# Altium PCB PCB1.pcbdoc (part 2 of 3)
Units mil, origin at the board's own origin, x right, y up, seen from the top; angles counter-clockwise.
Board outline 3256.12 x 1802.31 mil, 4 copper layers (Top Layer, Inner1, Inner2, Bottom Layer); 101 components, 70 nets, 295 pads, 151 vias.
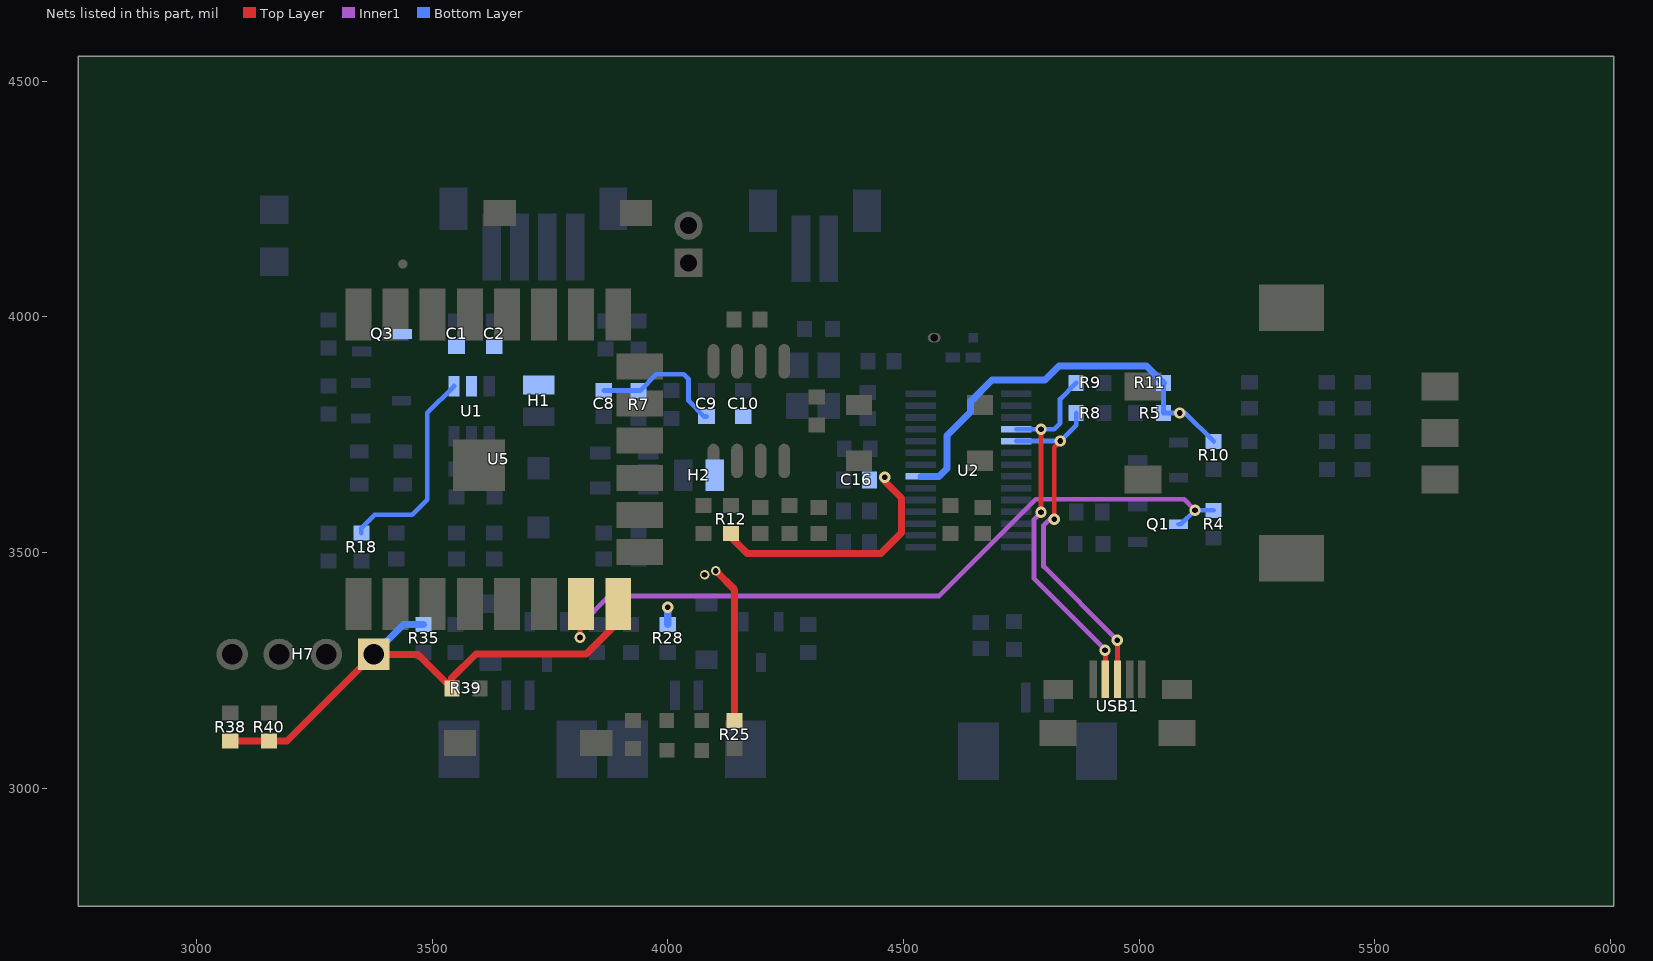
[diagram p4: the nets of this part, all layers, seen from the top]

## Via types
v1: diameter 20, hole 12.01, Top Layer to Bottom Layer, 104 vias
v2: diameter 24.02, hole 12.01, Top Layer to Bottom Layer, 44 vias
v3: diameter 20, hole 12, Top Layer to Bottom Layer, 3 vias

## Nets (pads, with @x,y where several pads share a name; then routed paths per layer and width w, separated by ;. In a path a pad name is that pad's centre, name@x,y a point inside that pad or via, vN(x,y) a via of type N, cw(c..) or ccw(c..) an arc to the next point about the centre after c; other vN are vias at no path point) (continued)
TXD: Q1.3 R4.2 U5.7 | length 1609.7
  Top Layer w10: v2(3814.01,3320) 3814.01,3388.7 U5.7@3816.23,3390.91
  Inner1 w10: v2(3814.01,3320) 3814.01,3346 3876.01,3408 4575.72,3408 4781.01,3613.29 5095.06,3613.29 v2(5118.35,3590)
  Bottom Layer w10: Q1.3@5083.37,3560 5088.35,3560 v2(5118.35,3590) 5118.69,3589.66 R4.2@5158.01,3589.66
USB_DM: R9.1 U2.18 USB1.2 | length 795.9
  Top Layer w10: v2(4791.83,3585.18) v2(4791.83,3761.5) ; v2(4927.59,3292.49) 4928.41,3291.67 USB1.2@4928.41,3231.18
  Inner1 w10: v2(4791.83,3585.18) 4777,3570.35 4777,3444.63 v2@4927.59,3294.03
  Bottom Layer w10: U2.18@4739.19,3761.5 v2(4791.83,3761.5) 4819.51,3761.5 4832.01,3774 4832.01,3825.66 R9.1@4866.35,3860
USB_DP: R8.1 U2.19 USB1.3 | length 757.6
  Top Layer w10: v2(4819.68,3570.6) 4819.68,3723.68 v2(4832.51,3736.5) ; v2(4953.57,3314.11) 4954.01,3313.68 USB1.3@4954.01,3231.18
  Inner1 w10: v2(4819.68,3570.6) 4809.77,3570.6 4797.08,3557.91 4797.08,3470.61 v2(4953.57,3314.11)
  Bottom Layer w10: U2.19@4739.19,3736.5 v2(4832.51,3736.5) 4866.35,3770.34 R8.1@4866.35,3796
VCC: C8.2 C9.2 C10.2 H2.2 H7.1 R7.2 R25.2 R28.2 R35.2 R38.2 R39.2 R40.2 U5.8 | length 1836.8
  Top Layer w15: R38.2@3072.01,3100.34 R40.2@3154.01,3100.34 3192.35,3100.34 H7.1@3376.01,3284 3470.35,3284 R39.2@3541.35,3213 ; R39.2@3542.35,3212 R39.2@3541.35,3213 ; U5.8@3894.97,3390.91 3893.97,3389.91 3893.97,3351.96 3827.01,3285 3593.01,3285 3541.35,3233.34 R39.2@3541.35,3213 ; v3(4102.01,3461) 4142.01,3421 R25.2@4142.01,3143.66
  Bottom Layer w10: C8.2@3864.01,3843.56 3937.92,3843.56 R7.2@3938.01,3843.47 3941.48,3843.47 3976.01,3878 4034.01,3878 4044.01,3868 4044.01,3822 4077.56,3788.44 C9.2@4082.06,3788.44
  Bottom Layer w15: H7.1@3376.01,3284 3439.67,3347.66 R35.2@3482.01,3347.66 ; R28.2@4000.01,3347.66 v2(4000.01,3384)
  other v3: 4078.01,3453
VDDIO: C16.2 R5.1 R10.1 R11.1 R12.1 U2.7 | length 1411.5
  Top Layer w15: R12.1@4134.01,3540.53 4134.01,3532.53 4168.14,3498.4 4452.63,3498.4 4496.14,3541.91 4496.14,3615.87 4460.01,3652 v2(4460.01,3660)
  Bottom Layer w10: R11.1@5051.67,3860 R5.1@5051.67,3796 v2(5086.01,3796) 5097.67,3796 R10.1@5158.01,3735.66
  Bottom Layer w15: U2.7@4536.83,3661.5 4575.51,3661.5 4592.01,3678 4592.01,3748 4642.01,3798 4642.01,3820 4688.01,3866 4800.01,3866 4830.01,3896 5015.67,3896 R11.1@5051.67,3860
VIN: C1.2 C2.2 H1.1 Q3.3 R18.2 U1.4 U1.5 | length 440
  Bottom Layer w10: R18.2@3350.01,3541.47 3350.01,3552 3378.01,3580 3458.01,3580 3490.01,3612 3490.01,3796.55 U1.4@3546.61,3853.15
pads on no net: H5.3 H5.4 H6.5 H6.6 H8.3 H8.4 H9.3 H9.4 SW1.2 SW2. U1.6 U2.5 U2.10 U4.7 U5.1 U5.11 U5.12 U5.14 U5.17 U5.18 U5.19 U5.20 U5.21 U5.22 U5.23 USB1.4 USB1.6 USB1.7 USB1.8 USB1.9

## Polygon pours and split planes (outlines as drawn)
GND on Bottom Layer (solid, remove dead copper, pour order 2): 3000,4023.76 3228.61,4023.76 3228.61,3371.05 3000,3371.05 3000,3002.82 5753.19,3002.82 5756.01,3000 5756.01,4302.03 5547,4302.03 5547,3966 4456.01,3966 4456.01,4302.24 3000,4302.24
GND on Top Layer (solid, remove dead copper, pour order 0): 3000,4023.76 3228.61,4023.76 3228.61,3371.05 3000,3371.05 3000,3002.82 5753.19,3002.82 5756.01,3000 5756.01,4302.03 5547,4302.03 5547,3966 4456.01,3966 4456.01,4302.24 3000,4302.24

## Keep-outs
Board Outline Layer:
  region: 5267.93,3120.93 cw(c5224.62,3120.93) 5181.32,3120.93 cw(c5224.62,3120.93)
  region: 5681.32,4183.94 cw(c5638.01,4183.94) 5594.7,4183.94 cw(c5638.01,4183.94)
  region: 3378.17,4183.94 cw(c3334.86,4183.94) 3291.55,4183.94 cw(c3334.86,4183.94)
  region: 3502.18,3120.93 cw(c3472.66,3120.93) 3443.13,3120.93 cw(c3472.66,3120.93)
  region: 3378.17,3120.93 cw(c3334.86,3120.93) 3291.55,3120.93 cw(c3334.86,3120.93)
  region: 3443.13,4183.94 cw(c3472.66,4183.94) 3502.18,4183.94 cw(c3472.66,4183.94)
  region: 5471.13,4183.94 cw(c5500.66,4183.94) 5530.18,4183.94 cw(c5500.66,4183.94)
  lines w1: 3291.55,3120.93 ccw(c3334.86,3120.93) 3378.17,3120.93 ccw(c3334.86,3120.93) 3291.55,3120.93 ; 3291.55,4183.94 ccw(c3334.86,4183.94) 3378.17,4183.94 ccw(c3334.86,4183.94) 3291.55,4183.94 ; 3443.13,3120.93 ccw(c3472.66,3120.93) 3502.18,3120.93 ccw(c3472.66,3120.93) 3443.13,3120.93 ; 3443.13,4183.94 cw(c3472.66,4183.94) 3502.18,4183.94 cw(c3472.66,4183.94) 3443.13,4183.94 ; 5181.32,3120.93 ccw(c5224.62,3120.93) 5267.93,3120.93 ccw(c5224.62,3120.93) 5181.32,3120.93 ; 5471.13,4183.94 cw(c5500.66,4183.94) 5530.18,4183.94 cw(c5500.66,4183.94) 5471.13,4183.94 ; 5594.7,4183.94 ccw(c5638.01,4183.94) 5681.32,4183.94 ccw(c5638.01,4183.94) 5594.7,4183.94
  lines w3.9: 3000,3002.82 3000,3371.05 3228.61,3371.05 3228.61,4023.76 3000,4023.76 3000,4302.03
  lines w3.94: 3000.01,4302 4548.55,4302.25 ccw(c5048.06,5262.81) 5547.22,4302.07 5756.12,4302.03 5756.12,3317.78 5271.12,3002.82 4537.6,3002.82 4537.6,3046.31 ccw(c4380.12,3046.64) 4222.64,3046.34 4222.72,3002.82 3000.21,3002.82

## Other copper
Top Layer:
  region net VCC: 3866.01,3446 4012.01,3446 4038.01,3472 4110.01,3472 4116.01,3466 4116.01,3438 4110.01,3432 4050.01,3432 4034.01,3416 4034.01,3350 4020.01,3336 3866.01,3336
  region net $1N6443: 4189.51,3633.81 4204.51,3633.81 ccw(c4236.58,3633.81) 4213.72,3611.31 4178.29,3611.31 ccw(c4161.33,3633.81)
  region net DACL: 4352.72,3594.54 4352.72,3584.54 ccw(c4352.72,3558.36) 4337.72,3579.81 4337.72,3602.04 ccw(c4352.72,3613.29)
  region net $1N6492: 4279.79,3533.03 4279.79,3548.03 ccw(c4279.79,3583.15) 4302.29,3556.19 4302.29,3524.69 ccw(c4279.79,3498.52)
  region net VCC: 3431.97,3291.5 3431.97,3276.5 ccw(c3431.97,3248.38) 3409.47,3265.25 3409.47,3302.75 ccw(c3431.97,3319.62)
  region net VCC: 3345.19,3242.58 3334.59,3253.19 ccw(c3302.77,3277.05) 3342.54,3277.05 3369.06,3250.54 ccw(c3369.06,3210.76)
  region net LOG_RXD: 3183.51,3238.44 3168.51,3238.44 3168.4,3240.79 3168.11,3242.86 3167.64,3244.69 3166.99,3246.31 3166.2,3247.76 3165.26,3249.07 3163.01,3251.4 3160.34,3253.58 3157.37,3255.87 3154.19,3258.54 3150.91,3261.87 3201.1,3261.87 3197.82,3258.54 3194.64,3255.87 3191.67,3253.58 3189.01,3251.4 3186.75,3249.07 3185.82,3247.76 3185.02,3246.31 3184.38,3244.69 3183.9,3242.86 3183.61,3240.79
  region net LOG_RXD: 3196.01,3317.5 3222.16,3302.5 3220.58,3302.4 3219.1,3302.11 3217.72,3301.64 3216.46,3301 3215.29,3300.21 3214.23,3299.28 3213.28,3298.23 3212.43,3297.05 3211.05,3294.42 3210.09,3291.47 3209.56,3288.32 3209.45,3285.07 3170.44,3317 3174.27,3317.56 3177.55,3317.87 3180.45,3317.98 3183.16,3317.95 3188.81,3317.69
  region net LOG_TXD: 3083.51,3238.44 3068.51,3238.44 3068.4,3240.79 3068.11,3242.86 3067.64,3244.69 3066.99,3246.31 3066.2,3247.76 3065.26,3249.07 3063.01,3251.4 3060.34,3253.58 3057.37,3255.87 3054.19,3258.54 3050.91,3261.87 3101.1,3261.87 3097.82,3258.54 3094.64,3255.87 3091.67,3253.58 3089.01,3251.4 3086.75,3249.07 3085.82,3247.76 3085.02,3246.31 3084.38,3244.69 3083.9,3242.86 3083.61,3240.79
  region net LOG_TXD: 3102.92,3321.52 3113.52,3310.91 3111.94,3309.18 3110.68,3307.51 3109.72,3305.88 3109.03,3304.28 3108.57,3302.69 3108.31,3301.1 3108.25,3297.86 3108.59,3294.44 3109.08,3290.72 3109.43,3286.58 3109.4,3281.9 3073.91,3317.4 3078.58,3317.43 3082.72,3317.07 3086.44,3316.59 3089.87,3316.24 3093.11,3316.3 3094.7,3316.56 3096.28,3317.02 3097.89,3317.72 3099.52,3318.68 3101.19,3319.93
  region net $1N6556: 4204.51,3954.49 4189.51,3954.49 ccw(c4158.55,3954.49) 4179.81,3976.99 4211.31,3976.99 ccw(c4245.12,3954.49)
  region net +5V: 4108.72,3984.5 4108.72,3999.5 ccw(c4108.72,4016.48) 4124.7,4010.75 4124.7,3976.99 ccw(c4108.72,3963.74)
  region net $1N8074: 4102.76,3085.53 4102.76,3075.53 ccw(c4102.76,3056.78) 4087.76,3068.03 4087.76,3093.03 ccw(c4102.76,3104.28)
  region net $1N8184: 3967.4,3079.34 3967.4,3089.34 ccw(c3967.4,3109.03) 3982.4,3096.28 3982.4,3071.84 ccw(c3967.4,3060.59)
  region net $1N6373: 4115.51,3607.35 4115.51,3592.35 ccw(c4115.51,3557.94) 4093.01,3583.98 4093.01,3615.73 ccw(c4115.51,3641.76)
  region net $1N6373: 4089.23,3623.68 4100.97,3614.21 ccw(c4132.79,3590.35) 4093.01,3590.35 4065.36,3615.73 ccw(c4065.36,3655.5)
  region net DACR: 4044,3536.01 4044,3546.01 ccw(c4044,3564.76) 4059,3553.51 4059,3528.51 ccw(c4044,3517.26)
  region net $1N6373: 4094.5,3592.35 4094.5,3607.35 ccw(c4094.5,3641.76) 4117,3615.73 4117,3583.98 ccw(c4094.5,3557.94)
  region net VDDIO: 4158.97,3518.18 4140.05,3515.89 ccw(c4117,3489.99) 4117,3524.66 4151.01,3542.04 ccw(c4190.79,3542.04)
  region net $1N6486: 4239.51,3638.23 4254.51,3638.23 ccw(c4282.63,3638.23) 4265.76,3615.73 4241,3615.73 ccw(c4070.6,3615.73)
  region net $1N6492: 4297.51,3548.03 4297.51,3533.03 ccw(c4297.51,3498.62) 4275.01,3524.66 4275.01,3556.41 ccw(c4297.51,3582.44)
  region net SPK-: 4287.16,3844.37 4302.43,3857.38 ccw(c4333.01,3890.95) 4333.01,3845.54 4299,3813.78 ccw(c4253.58,3813.78)
  region net $1N6486: 4276.5,3762.84 4276.5,3777.84 ccw(c4276.5,3812.25) 4299,3786.22 4299,3754.46 ccw(c4276.5,3728.43)
  region net VCC: 4134.51,3182.04 4149.51,3182.04 ccw(c4180.88,3182.04) 4159.01,3159.54 4125,3159.54 ccw(c4103.13,3182.04)
  region net $1N8074: 4110,3075.53 4110,3085.53 ccw(c4110,3104.28) 4125,3093.03 4125,3068.46 ccw(c4110,3056.06)
  region net SPK_LED: 3918.51,3175.45 3933.51,3175.45 ccw(c3951.59,3175.45) 3943.01,3159.54 3909,3159.54 ccw(c3900.42,3175.45)
  region net $1N8184: 3958.01,3089.34 3958.01,3079.34 ccw(c3958.01,3060.59) 3943.01,3071.84 3943.01,3096.84 ccw(c3958.01,3108.09)
  region net VCC: 3111.51,3107.84 3111.51,3092.84 ccw(c3111.51,3058.43) 3089.01,3084.46 3089.01,3116.22 ccw(c3111.51,3142.25)
  region net LOG_TXD: 3068.51,3198.04 3083.51,3198.04 ccw(c3132.22,3198.04) 3089.01,3175.54 3057.26,3175.54 ccw(c3040.38,3198.04)
  region net VCC: 3192.35,3107.84 3192.35,3092.84 ccw(c3192.35,3061.49) 3171.01,3084.46 3171.01,3116.22 ccw(c3192.35,3139.19)
  region net VCC: 3114.5,3092.84 3114.5,3107.84 ccw(c3114.5,3142.25) 3137,3116.22 3137,3084.46 ccw(c3114.5,3058.43)
  region net LOG_RXD: 3167.23,3183.49 3178.97,3174.02 ccw(c3210.79,3150.15) 3171.01,3150.15 3143.36,3175.54 ccw(c3143.36,3215.31)
  region net EC11_D: 5062.42,3660.27 5062.42,3650.27 ccw(c5062.42,3631.52) 5047.42,3642.77 5047.42,3667.77 ccw(c5062.42,3679.02)
  region net EC11_A: 5589.38,3696.79 5607.62,3692.69 ccw(c5629.7,3714.77) 5620.94,3684.8 5598.6,3684.8 ccw(c5548.09,3655.51)
  region net EC11_B: 5583.6,3847.13 5583.6,3857.13 ccw(c5583.6,3875.88) 5598.6,3864.63 5598.6,3839.63 ccw(c5583.6,3828.38)
  region net BOOT: 3449.82,4119.5 3449.82,4104.5 3447.65,4104.4 3445.62,4104.13 3442.07,4103.33 3439.44,4102.52 3438.01,4102.16 3438.01,4121.84 3439.44,4121.48 3442.07,4120.67 3445.62,4119.87 3447.65,4119.6
  region net RXD: 3821.23,3936.22 3811.23,3936.22 ccw(c3794.88,3936.22) 3803.73,3949.97 3828.73,3949.97 ccw(c3837.57,3936.22)
  region net VCC: 3880.45,3327.84 3859.45,3328.05 ccw(c3827.63,3351.92) 3867.41,3351.92 3904.32,3335.8 ccw(c3904.32,3296.02)
  region net TXD: 3819.01,3320.8 3809.01,3320.8 ccw(c3790.26,3320.8) 3801.51,3335.8 3826.51,3335.8 ccw(c3837.76,3320.8)
  region net SPK_LED: 3744.99,3318 3729.99,3318 ccw(c3710.28,3318) 3718.74,3335.8 3756.24,3335.8 ccw(c3764.69,3318)
  region net POWER_IO: 3651.24,3468.53 3666.24,3468.53 ccw(c3694.36,3468.53) 3677.49,3446.03 3639.99,3446.03 ccw(c3623.11,3468.53)
  region net POWER_SW: 3572.51,3468 3587.51,3468 ccw(c3614.58,3468) 3598.76,3446.03 3561.26,3446.03 ccw(c3545.43,3468)
  region net EN: 3493.77,3454.74 3508.77,3454.74 ccw(c3520.02,3457.65) 3520.02,3446.03 3482.52,3446.03 ccw(c3482.52,3457.65)
  region net POWER_ADC: 3418.51,3458 3433.51,3458 ccw(c3445.5,3458) 3444.76,3446.03 3407.26,3446.03 ccw(c3406.52,3458)
  region net LOG_TXD: 3296.24,3946.94 3304.38,3976.29 ccw(c3271.26,4009.41) 3316.22,3996.28 3316.22,3958.78 ccw(c3329.35,3913.82)
  region net LOG_RXD: 3406.62,3942.01 3387,3943.6 ccw(c3355.18,3967.47) 3394.96,3967.47 3430.49,3949.97 ccw(c3430.49,3910.19)
  region net POWER_LED: 3587.51,3936 3572.51,3936 ccw(c3558.21,3936) 3561.26,3949.97 3598.76,3949.97 ccw(c3601.8,3936)
  region net $1N6373: 4104.51,3647.58 4089.51,3647.58 4089.3,3651.73 4088.74,3655.7 4087.95,3659.38 4087.06,3662.67 4085.37,3667.72 4084.6,3670.08 4109.41,3670.08 4108.64,3667.72 4106.96,3662.67 4106.06,3659.38 4105.27,3655.7 4104.72,3651.73
  region net $1N6443: 4189.41,3704.39 4189.41,3684.39 4183.81,3684.39 4178.39,3684.26 4173.32,3683.82 4170.98,3683.41 4168.78,3682.86 4166.76,3682.13 4164.94,3681.2 4163.34,3680.04 4161.99,3678.64 4160.89,3676.97 4160.08,3675 4159.58,3672.71 4159.41,3670.08 4159.41,3718.7 4159.58,3716.07 4160.08,3713.78 4160.89,3711.81 4161.99,3710.14 4163.34,3708.74 4164.94,3707.58 4166.76,3706.65 4168.78,3705.92 4170.98,3705.37 4173.32,3704.96 4178.39,3704.52 4183.81,3704.39
  region net $1N6443: 4204.51,3647.58 4189.51,3647.58 4189.3,3651.73 4188.74,3655.7 4187.95,3659.38 4187.06,3662.67 4185.37,3667.72 4184.6,3670.08 4209.41,3670.08 4208.64,3667.72 4206.96,3662.67 4206.06,3659.38 4205.27,3655.7 4204.72,3651.73
  region net $1N6443: 4154.6,3684.39 4154.6,3704.39 4160.2,3704.39 4165.62,3704.52 4170.69,3704.96 4173.04,3705.37 4175.23,3705.92 4177.25,3706.65 4179.07,3707.58 4180.67,3708.74 4182.03,3710.14 4183.12,3711.81 4183.93,3713.78 4184.43,3716.07 4184.6,3718.7 4184.6,3670.08 4184.43,3672.71 4183.93,3675 4183.12,3676.97 4182.03,3678.64 4180.67,3680.04 4179.07,3681.2 4177.25,3682.13 4175.23,3682.86 4173.04,3683.41 4170.69,3683.82 4165.62,3684.26 4160.2,3684.39
  region net $1N6486: 4239.51,3741.2 4254.51,3741.2 4254.72,3737.05 4255.27,3733.08 4256.06,3729.4 4256.96,3726.11 4258.64,3721.06 4259.41,3718.7 4234.6,3718.7 4235.37,3721.06 4237.06,3726.11 4237.95,3729.4 4238.74,3733.08 4239.3,3737.05
  region net $1N6486: 4254.51,3647.58 4239.51,3647.58 4239.3,3651.73 4238.74,3655.7 4237.95,3659.38 4237.06,3662.67 4235.37,3667.72 4234.6,3670.08 4259.41,3670.08 4258.64,3667.72 4256.96,3662.67 4256.06,3659.38 4255.27,3655.7 4254.72,3651.73
  region net SPK+: 4066.01,3895.61 4066.01,3915.61 4069.47,3915.84 4072.83,3916.54 4075.98,3917.69 4078.79,3919.28 4080.04,3920.24 4081.17,3921.31 4082.16,3922.48 4083.01,3923.76 4083.68,3925.15 4084.19,3926.64 4084.5,3928.23 4084.6,3929.92 4084.6,3881.3 4084.5,3882.99 4084.19,3884.58 4083.68,3886.07 4083.01,3887.46 4082.16,3888.74 4081.17,3889.91 4080.04,3890.98 4078.79,3891.94 4075.98,3893.53 4072.83,3894.68 4069.47,3895.38
  region net $1N6556: 4189.51,3952.42 4204.51,3952.42 4204.72,3948.27 4205.27,3944.3 4206.06,3940.62 4206.96,3937.33 4208.64,3932.28 4209.41,3929.92 4184.6,3929.92 4185.37,3932.28 4187.06,3937.33 4187.95,3940.62 4188.74,3944.3 4189.3,3948.27
  region net SPK-: 4237.01,3959.92 4257.01,3959.92 4257.11,3954.37 4257.38,3949.05 4258.21,3939.67 4259.41,3929.92 4234.6,3929.92 4235.81,3939.67 4236.63,3949.05 4236.9,3954.37
  region net SPK-: 4270.01,3889.79 4263.63,3867.9 4262.11,3869.13 4260.3,3870.13 4258.25,3870.95 4256.03,3871.61 4251.26,3872.62 4246.4,3873.47 4241.87,3874.46 4239.87,3875.1 4238.12,3875.9 4236.66,3876.87 4235.55,3878.07 4234.85,3879.54 4234.6,3881.3 4259.41,3921.61 4259.56,3917.51 4260.01,3913.22 4260.79,3908.86 4261.9,3904.54 4263.36,3900.36 4265.19,3896.44 4267.4,3892.88 4268.66,3891.27
  region net SPK-: 4084.37,4204 4085.32,4184 4083.61,4183.93 4082,4183.71 4079.05,4182.91 4076.37,4181.65 4073.89,4180.03 4071.52,4178.1 4069.19,4175.96 4064.32,4171.29 4063.37,4216.28 4068.38,4211.77 4070.7,4209.7 4073.03,4207.84 4075.46,4206.27 4078.1,4205.06 4081.04,4204.28
  region net $1N14735: 4632.29,3593.85 4632.29,3605.85 ccw(c4632.29,3638.28) 4650.29,3611.31 4650.29,3584.85 ccw(c4632.29,3571.35)
  region net +5V: 4635.29,3535.53 4635.29,3545.53 ccw(c4635.29,3564.28) 4650.29,3553.03 4650.29,3528.03 ccw(c4635.29,3516.78)
  region net +5V: 4700.72,3547.44 4700.72,3537.44 ccw(c4700.72,3518.69) 4685.72,3529.94 4685.72,3554.94 ccw(c4700.72,3566.19)
  region net +5V: 4605.01,3509.66 4595.01,3509.66 ccw(c4576.26,3509.66) 4587.51,3524.66 4612.51,3524.66 ccw(c4623.76,3509.66)
  region net +5V: 4632.01,3545.53 4632.01,3535.53 ccw(c4632.01,3516.78) 4617.01,3528.03 4617.01,3553.03 ccw(c4632.01,3564.28)
  region net $1N14735: 4576.63,3614.74 4586.25,3622.09 ccw(c4605.34,3647.55) 4605.34,3615.73 4583,3595.65 ccw(c4551.18,3595.65)
  region net $1N14735: 4635.01,3605.85 4635.01,3593.85 ccw(c4635.01,3571.35) 4617.01,3584.85 4617.01,3614.85 ccw(c4635.01,3628.35)
  region net VCC: 3533.85,3233.34 3548.85,3233.34 ccw(c3558.22,3241.32) 3558.22,3229.01 3526.47,3229.01 ccw(c3526.47,3237.45)
  region net VCC: 3518.52,3225.22 3527.99,3236.96 ccw(c3551.85,3268.78) 3551.85,3229.01 3526.47,3201.36 ccw(c3486.7,3201.36)
  region net EN: 3609.17,3180.98 3594.17,3180.98 ccw(c3578.26,3180.98) 3585.79,3194.99 3617.54,3194.99 ccw(c3625.08,3180.98)
  region net $1N14735: 4451.61,3700.95 4451.61,3688.95 ccw(c4451.61,3666.45) 4433.61,3679.95 4433.61,3709.95 ccw(c4451.61,3723.45)
  region net KEY_IO: 4657.01,3731.6 4667.01,3731.6 ccw(c4685.76,3731.6) 4674.51,3716.6 4649.51,3716.6 ccw(c4638.26,3731.6)
  region net BOOT: 3618.61,4184.49 3601.31,4188.4 ccw(c3569.49,4212.26) 3609.26,4212.26 3642.47,4192.44 ccw(c3642.47,4152.67)
  region net EN: 3584.42,3131.51 3601.72,3127.6 ccw(c3633.54,3103.74) 3593.77,3103.74 3560.56,3123.56 ccw(c3560.56,3163.33)
  region net +5V: 4897.81,3285.55 4907.81,3285.55 ccw(c4948.39,3285.55) 4910.68,3270.55 4894.93,3270.55 ccw(c4857.22,3285.55)
  region net USB_DM: 4923.41,3285.55 4933.41,3285.55 ccw(c4973.99,3285.55) 4936.28,3270.55 4920.53,3270.55 ccw(c4882.82,3285.55)
  region net USB_DP: 4949.01,3285.55 4959.01,3285.55 ccw(c4999.59,3285.55) 4961.88,3270.55 4946.13,3270.55 ccw(c4908.42,3285.55)
  region net +5V: 4444.35,3474.98 4444.35,3464.98 4443.21,3464.89 4442.07,3464.63 4439.86,3463.72 4437.79,3462.44 4435.94,3460.97 4435.94,3478.98 4437.79,3477.51 4439.86,3476.23 4442.07,3475.32 4443.21,3475.07
  region net +5V: 4411.65,3462.48 4411.65,3477.48 4414.02,3477.4 4416.17,3477.4 4417.18,3477.53 4418.15,3477.81 4419.11,3478.28 4420.06,3478.98 4420.05,3460.97 4419.11,3461.67 4418.15,3462.14 4417.17,3462.42 4416.17,3462.55 4414.02,3462.55
  region net +5V: 5239.01,3627.65 5229.01,3627.65 5228.92,3628.79 5228.66,3629.92 5227.75,3632.14 5226.47,3634.21 5225,3636.06 5243.01,3636.06 5241.54,3634.21 5240.26,3632.14 5239.35,3629.92 5239.1,3628.79
  region net DACL: 4811.82,3506.5 4811.82,3516.5 4812.96,3516.59 4814.1,3516.84 4816.31,3517.75 4818.38,3519.03 4820.23,3520.51 4820.23,3502.49 4818.38,3503.97 4816.31,3505.25 4814.1,3506.16 4812.96,3506.41
  region net VDDIO: 4475.41,3647.2 4458.6,3642.8 4457.77,3643.76 4457.18,3644.71 4456.35,3646.54 4455.41,3648.24 4454.69,3649.04 4453.7,3649.78 4470.51,3654.18 4470.05,3653 4470.07,3652.02 4470.47,3651.18 4471.18,3650.44 4473.19,3648.99 4474.31,3648.17
  region net +5V: 5172.41,3537.44 5170.47,3547.44 5171.6,3547.54 5172.75,3547.82 5175.03,3548.81 5177.13,3550.22 5178.87,3551.83 5180.81,3533.92 5178.88,3535.22 5176.82,3536.34 5174.66,3537.14 5173.54,3537.36
  region net +5V: 5195.76,3558.83 5202.84,3551.76 5202.09,3550.89 5201.47,3549.91 5200.55,3547.7 5199.99,3545.33 5199.72,3542.98 5186.99,3555.72 5189.33,3555.98 5191.71,3556.54 5193.91,3557.47 5194.9,3558.09
  region net KEY_IO: 4667.01,3717.65 4657.01,3717.65 4656.92,3718.79 4656.66,3719.92 4655.75,3722.14 4654.47,3724.21 4653,3726.06 4671.01,3726.06 4669.54,3724.21 4668.26,3722.14 4667.35,3719.92 4667.1,3718.79
  region net USB_DM: 4796.83,3745.15 4786.83,3745.15 4786.74,3746.29 4786.49,3747.42 4785.58,3749.64 4784.3,3751.71 4782.83,3753.56 4800.84,3753.56 4799.37,3751.71 4798.08,3749.64 4797.18,3747.42 4796.92,3746.29
  region net USB_DP: 4824.48,3721.4 4817.41,3728.48 4818.15,3729.34 4818.77,3730.33 4819.7,3732.53 4820.26,3734.91 4820.52,3737.25 4833.26,3724.52 4830.91,3724.25 4828.54,3723.69 4826.33,3722.77 4825.35,3722.15
  region net TXD: 3809.01,3336.35 3819.01,3336.35 3819.1,3335.21 3819.35,3334.08 3820.26,3331.86 3821.54,3329.79 3823.01,3327.94 3805,3327.94 3806.47,3329.79 3807.75,3331.86 3808.66,3334.08 3808.92,3335.21
  region net +5V: 4034,3502.5 4038.62,3487.5 4037.13,3487.36 4035.62,3487 4032.57,3485.82 4029.56,3484.44 4026.63,3483.35 4022.01,3502.8 4024.8,3503.04 4027.98,3502.9 4031.17,3502.64
  region net +5V: 4010.22,3496.18 4020.82,3506.79 4022.45,3505.31 4024.12,3504.05 4027.28,3502.1 4029.77,3500.82 4031.08,3500.07 4016.93,3485.93 4016.18,3487.23 4014.9,3489.73 4012.96,3492.89 4011.7,3494.55
  region net VCC: 4115.79,3457.82 4105.19,3447.21 4103.56,3448.69 4101.9,3449.95 4098.74,3451.9 4096.24,3453.18 4094.93,3453.93 4109.08,3468.07 4109.83,3466.77 4111.11,3464.27 4113.05,3461.11 4114.32,3459.45
  region net RXD: 3811.23,3952.51 3821.23,3952.18 3821.31,3951.04 3821.56,3949.91 3822.45,3947.71 3823.71,3945.64 3825.16,3943.78 3807.15,3944.11 3808.64,3945.93 3809.95,3948.01 3810.88,3950.24 3811.13,3951.37
  region net USB_DM: 4786.83,3601.53 4796.83,3601.53 4796.92,3600.39 4797.18,3599.26 4798.08,3597.04 4799.37,3594.97 4800.84,3593.12 4782.83,3593.12 4784.3,3594.97 4785.58,3597.04 4786.49,3599.26 4786.74,3600.39
  region net USB_DP: 4814.68,3586.95 4824.68,3586.95 4824.77,3585.82 4825.03,3584.68 4825.93,3582.47 4827.22,3580.39 4828.69,3578.55 4810.68,3578.55 4812.15,3580.39 4813.43,3582.47 4814.34,3584.68 4814.59,3585.82
  region net USB_DP: 4959.01,3298.09 4949.01,3297.45 4948.91,3298.58 4948.65,3299.72 4947.71,3301.96 4946.38,3304.04 4944.86,3305.85 4962.86,3306.5 4961.44,3304.62 4960.21,3302.56 4959.34,3300.36 4959.09,3299.23
  region net USB_DM: 4933.41,3276.77 4923.41,3275.55 4923.31,3276.68 4923.04,3277.83 4922.07,3280.09 4920.71,3282.17 4919.14,3283.95 4937.11,3285.18 4935.75,3283.27 4934.56,3281.21 4933.72,3279.03 4933.49,3277.91
  region net EC11_B: 5405.46,3785 5412.53,3777.93 5411.79,3777.06 5411.17,3776.08 5410.25,3773.87 5409.69,3771.5 5409.42,3769.15 5396.69,3781.89 5399.03,3782.16 5401.4,3782.71 5403.61,3783.64 5404.59,3784.26
  region net EC11_A: 5490.3,3776.25 5490.3,3766.25 5489.16,3766.16 5488.03,3765.9 5485.81,3765 5483.74,3763.71 5481.89,3762.24 5481.89,3780.25 5483.74,3778.78 5485.81,3777.5 5488.03,3776.59 5489.16,3776.34
  region net EC11_D: 5188.62,3694.57 5181.55,3701.65 5182.29,3702.51 5182.92,3703.49 5183.84,3705.7 5184.4,3708.08 5184.66,3710.42 5197.4,3697.69 5195.06,3697.42 5192.68,3696.86 5190.47,3695.94 5189.49,3695.31
  region net DACL: 4636.16,3513.66 4643.23,3506.59 4642.49,3505.72 4641.87,3504.74 4640.94,3502.53 4640.39,3500.16 4640.12,3497.81 4627.38,3510.55 4629.73,3510.81 4632.1,3511.37 4634.31,3512.3 4635.29,3512.92
  region net DACL: 4450.68,3581.16 4457.75,3588.23 4458.62,3587.49 4459.6,3586.86 4461.81,3585.94 4464.18,3585.38 4466.52,3585.12 4453.79,3572.38 4453.52,3574.73 4452.96,3577.1 4452.04,3579.31 4451.42,3580.29
  region net DACR: 4058.45,3546.01 4058.45,3536.01 4057.32,3535.92 4056.18,3535.66 4053.97,3534.75 4051.89,3533.47 4050.05,3532 4050.05,3550.01 4051.89,3548.54 4053.97,3547.26 4056.18,3546.35 4057.32,3546.1
  region net +5V: 4125.07,3999.5 4125.07,3984.5 4122.7,3984.58 4120.55,3984.58 4119.54,3984.44 4118.57,3984.16 4117.61,3983.69 4116.66,3982.99 4116.66,4001.01 4117.61,4000.31 4118.57,3999.84 4119.54,3999.56 4120.55,3999.42 4122.7,3999.42
  region net +5V: 4102.46,3975.14 4091.86,3985.74 4093.59,3987.37 4095.11,3988.88 4095.73,3989.69 4096.22,3990.58 4096.56,3991.59 4096.74,3992.75 4109.47,3980.02 4108.31,3979.84 4107.3,3979.5 4106.41,3979 4105.6,3978.39 4104.09,3976.87
  region net SPK+: 4080.42,3915.61 4080.42,3895.61 4077.77,3895.52 4075.26,3895.3 4070.88,3894.61 4067.67,3893.92 4066.01,3893.6 4066.01,3917.62 4067.67,3917.3 4070.88,3916.61 4075.26,3915.92 4077.77,3915.7
  region net POWER_ADC: 3433.51,3441.65 3418.51,3441.65 3418.58,3444.03 3418.58,3446.17 3418.45,3447.18 3418.17,3448.16 3417.7,3449.11 3417,3450.06 3435.01,3450.06 3434.31,3449.11 3433.84,3448.16 3433.56,3447.18 3433.43,3446.17 3433.43,3444.03
  region net POWER_IO: 3328.35,3757.5 3328.35,3742.5 3325.98,3742.58 3323.84,3742.58 3322.83,3742.44 3321.85,3742.16 3320.89,3741.69 3319.95,3740.99 3319.95,3759.01 3320.89,3758.31 3321.85,3757.84 3322.83,3757.56 3323.84,3757.42 3325.98,3757.42
  region net POWER_SW: 3454.87,3603.74 3444.26,3593.14 3442.64,3594.87 3441.12,3596.39 3440.32,3597 3439.43,3597.5 3438.42,3597.84 3437.25,3598.02 3449.99,3610.75 3450.16,3609.59 3450.51,3608.58 3451,3607.69 3451.62,3606.88 3453.14,3605.37
  region net POWER_LED: 3799.66,3892.5 3799.66,3907.5 3802.03,3907.42 3804.17,3907.42 3805.18,3907.56 3806.16,3907.84 3807.12,3908.31 3808.06,3909.01 3808.06,3890.99 3807.12,3891.69 3806.16,3892.16 3805.18,3892.44 3804.17,3892.58 3802.03,3892.58
  region net EN: 3594.17,3197.33 3609.17,3197.33 3609.09,3194.95 3609.09,3192.81 3609.22,3191.8 3609.5,3190.82 3609.97,3189.87 3610.67,3188.92 3592.66,3188.92 3593.36,3189.87 3593.83,3190.82 3594.11,3191.8 3594.24,3192.81 3594.24,3194.95
  region net EN: 3609.17,3164.63 3594.17,3164.63 3594.24,3167 3594.24,3169.15 3594.11,3170.16 3593.83,3171.13 3593.36,3172.09 3592.66,3173.04 3610.67,3173.04 3609.97,3172.09 3609.5,3171.13 3609.22,3170.16 3609.09,3169.15 3609.09,3167
  region net SPK_LED: 3729.99,3331.95 3744.99,3332.73 3744.92,3330.35 3744.96,3328.18 3745.11,3327.16 3745.42,3326.18 3745.92,3325.24 3746.66,3324.32 3728.66,3323.55 3729.33,3324.52 3729.77,3325.49 3730.02,3326.47 3730.12,3327.47 3730.08,3329.58
  region net SPK_LED: 3933.51,3159.11 3918.51,3159.11 3918.58,3161.48 3918.58,3163.62 3918.45,3164.63 3918.17,3165.61 3917.7,3166.57 3917,3167.51 3935.01,3167.51 3934.31,3166.57 3933.84,3165.61 3933.56,3164.63 3933.43,3163.62 3933.43,3161.48
  region net +5V: 4897.81,3507.44 ccw(c4847.81,3507.44) 4887.81,3537.44 4904.63,3542.44 4917.81,3537.44 ccw(c4957.81,3507.44) 4907.81,3507.44
Inner1:
  region net MUSIC_SW: 4389.01,3957.68 4375.01,3957.62 4374.98,3959.91 4374.76,3962.11 4374.16,3964.18 4373.66,3965.13 4372.99,3966.03 4391,3966.09 4390.33,3965.19 4389.83,3964.23 4389.24,3962.17 4389.03,3959.97
  region net MOTOR_PWM: 3866.35,3265 3866.35,3255 3865.22,3254.91 3864.08,3254.66 3861.87,3253.75 3859.79,3252.47 3857.95,3250.99 3857.95,3269.01 3859.79,3267.53 3861.87,3266.25 3864.08,3265.34 3865.22,3265.09
  region net MOTOR_PWM: 4463.98,3360.9 4456.91,3367.98 4457.65,3368.84 4458.27,3369.83 4459.2,3372.03 4459.76,3374.41 4460.02,3376.75 4472.76,3364.02 4470.41,3363.75 4468.04,3363.19 4465.83,3362.27 4464.85,3361.65
  region net DACL: 4844.52,3516.5 4844.52,3506.5 4843.38,3506.41 4842.25,3506.16 4840.03,3505.25 4837.96,3503.97 4836.11,3502.49 4836.11,3520.51 4837.96,3519.03 4840.03,3517.75 4842.25,3516.84 4843.38,3516.59
  region net DACL: 4929.66,3581 4929.66,3591 4930.8,3591.09 4931.93,3591.34 4934.14,3592.25 4936.22,3593.53 4938.06,3595.01 4938.06,3576.99 4936.22,3578.47 4934.14,3579.75 4931.93,3580.66 4930.8,3580.91
  region net MUSIC_SW: 4603.66,3729 4603.66,3743 4605.94,3743.03 4608.15,3743.24 4610.21,3743.84 4611.17,3744.34 4612.06,3745.01 4612.06,3726.99 4611.17,3727.66 4610.21,3728.16 4608.15,3728.76 4605.94,3728.97
  region net TXD: 5103.25,3598.02 5110.32,3605.1 5111.19,3604.35 5112.17,3603.73 5114.38,3602.81 5116.75,3602.25 5119.1,3601.98 5106.36,3589.25 5106.1,3591.59 5105.54,3593.97 5104.61,3596.17 5103.99,3597.16
  region net TXD: 3809.01,3336.35 3819.01,3336.35 3819.1,3335.21 3819.35,3334.08 3820.26,3331.86 3821.54,3329.79 3823.01,3327.94 3805,3327.94 3806.47,3329.79 3807.75,3331.86 3808.66,3334.08 3808.92,3335.21
  region net RXD: 5068.27,3690.78 5075.34,3697.85 5076.21,3697.11 5077.19,3696.49 5079.4,3695.56 5081.77,3695 5084.12,3694.74 5071.38,3682 5071.12,3684.35 5070.56,3686.72 5069.63,3688.93 5069.01,3689.91
  region net RXD: 3831.1,3927.98 3824.03,3920.9 3823.16,3921.65 3822.18,3922.27 3819.97,3923.19 3817.6,3923.75 3815.25,3924.02 3827.99,3936.75 3828.26,3934.41 3828.81,3932.03 3829.74,3929.83 3830.36,3928.84
  region net USB_DM: 4783.81,3570.08 4776.74,3577.16 4777.48,3578.02 4778.1,3579.01 4779.02,3581.21 4779.58,3583.59 4779.85,3585.93 4792.58,3573.2 4790.24,3572.93 4787.86,3572.37 4785.66,3571.45 4784.67,3570.83
  region net USB_DP: 4803.95,3557.72 4804.4,3572.31 4807.46,3575.2 4810.39,3578.21 4812.77,3560.79 4811.6,3561.4 4810.45,3561.62 4809.32,3561.51 4808.2,3561.1 4807.11,3560.47 4806.04,3559.66
  region net USB_DP: 4938.48,3322.14 4945.55,3329.21 4946.42,3328.47 4947.4,3327.85 4949.61,3326.92 4951.98,3326.36 4954.33,3326.1 4941.59,3313.36 4941.32,3315.71 4940.77,3318.08 4939.84,3320.29 4939.22,3321.27
  region net USB_DM: 4912.71,3301.84 4920.94,3307.76 4921.8,3307.01 4922.75,3306.38 4924.86,3305.42 4927.13,3304.78 4929.43,3304.36 4915.59,3292.83 4915.47,3295.2 4914.97,3297.66 4914.06,3299.96 4913.44,3300.97
  region net EC11_B: 5381.09,3764.91 5381.09,3774.91 5382.23,3775 5383.36,3775.25 5385.58,3776.16 5387.65,3777.44 5389.5,3778.91 5389.5,3760.9 5387.65,3762.37 5385.58,3763.65 5383.36,3764.56 5382.23,3764.82
  region net EC11_A: 5465.93,3756.15 5458.86,3763.22 5459.6,3764.09 5460.22,3765.07 5461.14,3767.28 5461.7,3769.66 5461.97,3772 5474.7,3759.26 5472.36,3759 5469.99,3758.44 5467.78,3757.52 5466.8,3756.89
  region net EC11_A: 4823.53,3793.57 4823.53,3783.57 4822.39,3783.48 4821.26,3783.23 4819.04,3782.32 4816.97,3781.04 4815.13,3779.57 4815.13,3797.58 4816.97,3796.11 4819.04,3794.83 4821.26,3793.92 4822.39,3793.66
  region net EC11_B: 4801.38,3817.07 4801.38,3807.07 4800.24,3806.98 4799.11,3806.73 4796.89,3805.82 4794.82,3804.54 4792.97,3803.07 4792.97,3821.08 4794.82,3819.61 4796.89,3818.32 4799.11,3817.42 4800.24,3817.16
  region net EC11_D: 5188.62,3694.57 5181.55,3701.65 5182.29,3702.51 5182.92,3703.49 5183.84,3705.7 5184.4,3708.08 5184.66,3710.42 5197.4,3697.69 5195.06,3697.42 5192.68,3696.86 5190.47,3695.94 5189.49,3695.31
  region net EC11_D: 3395.84,3720.39 3395.84,3710.39 3394.7,3710.3 3393.57,3710.04 3391.35,3709.13 3389.28,3707.85 3387.43,3706.38 3387.43,3724.39 3389.28,3722.92 3391.35,3721.64 3393.57,3720.73 3394.7,3720.48
  region net DACL: 4613.04,3506.59 4620.11,3513.66 4620.98,3512.92 4621.96,3512.3 4624.17,3511.37 4626.54,3510.81 4628.89,3510.55 4616.15,3497.81 4615.89,3500.16 4615.33,3502.53 4614.4,3504.74 4613.78,3505.72
  region net DACL: 4482.12,3578.13 4482.12,3568.13 4480.98,3568.04 4479.85,3567.79 4477.63,3566.88 4475.56,3565.6 4473.72,3564.13 4473.72,3582.14 4475.56,3580.67 4477.63,3579.38 4479.85,3578.48 4480.98,3578.22
  region net DACR: 4520.95,3500.99 4528.02,3508.06 4528.89,3507.32 4529.87,3506.7 4532.08,3505.78 4534.46,3505.22 4536.8,3504.95 4524.06,3492.22 4523.8,3494.56 4523.24,3496.93 4522.32,3499.14 4521.69,3500.12
  region net DACR: 4058.45,3546.01 4058.45,3536.01 4057.32,3535.92 4056.18,3535.66 4053.97,3534.75 4051.89,3533.47 4050.05,3532 4050.05,3550.01 4051.89,3548.54 4053.97,3547.26 4056.18,3546.35 4057.32,3546.1
  region net EN: 3584.8,3187.24 3595.41,3197.84 3597.03,3196.11 3598.55,3194.59 3599.36,3193.97 3600.25,3193.48 3601.25,3193.14 3602.42,3192.96 3589.68,3180.23 3589.51,3181.39 3589.16,3182.4 3588.67,3183.29 3588.05,3184.1 3586.53,3185.61
  region net EN: 3499.51,3447.65 3484.51,3447.65 3484.58,3450.03 3484.58,3452.17 3484.45,3453.18 3484.17,3454.16 3483.7,3455.11 3483,3456.06 3501.01,3456.06 3500.31,3455.11 3499.84,3454.16 3499.56,3453.18 3499.43,3452.17 3499.43,3450.03
  region net SPK_LED: 3744.26,3332.86 3754.87,3322.26 3753.14,3320.63 3751.62,3319.12 3751,3318.31 3750.51,3317.42 3750.16,3316.41 3749.99,3315.25 3737.25,3327.98 3738.42,3328.16 3739.43,3328.5 3740.32,3329 3741.12,3329.61 3742.64,3331.13
  region net SPK_LED: 3754.87,3309.74 3744.26,3299.14 3742.64,3300.87 3741.12,3302.39 3740.32,3303 3739.43,3303.5 3738.42,3303.84 3737.25,3304.02 3749.99,3316.75 3750.16,3315.59 3750.51,3314.58 3751,3313.69 3751.62,3312.88 3753.14,3311.37
  region net SPK_LED: 3909.26,3168.5 3910.07,3183.5 3912.45,3183.41 3914.56,3183.36 3915.55,3183.46 3916.53,3183.71 3917.5,3184.15 3918.48,3184.81 3917.66,3166.82 3916.75,3167.56 3915.81,3168.06 3914.83,3168.37 3913.81,3168.53 3911.64,3168.56
  region net SPK_LED: 3807.51,3657.65 3792.51,3657.65 3792.58,3660.03 3792.58,3662.17 3792.45,3663.18 3792.17,3664.16 3791.7,3665.11 3791,3666.06 3809.01,3666.06 3808.31,3665.11 3807.84,3664.16 3807.56,3663.18 3807.43,3662.17 3807.43,3660.03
